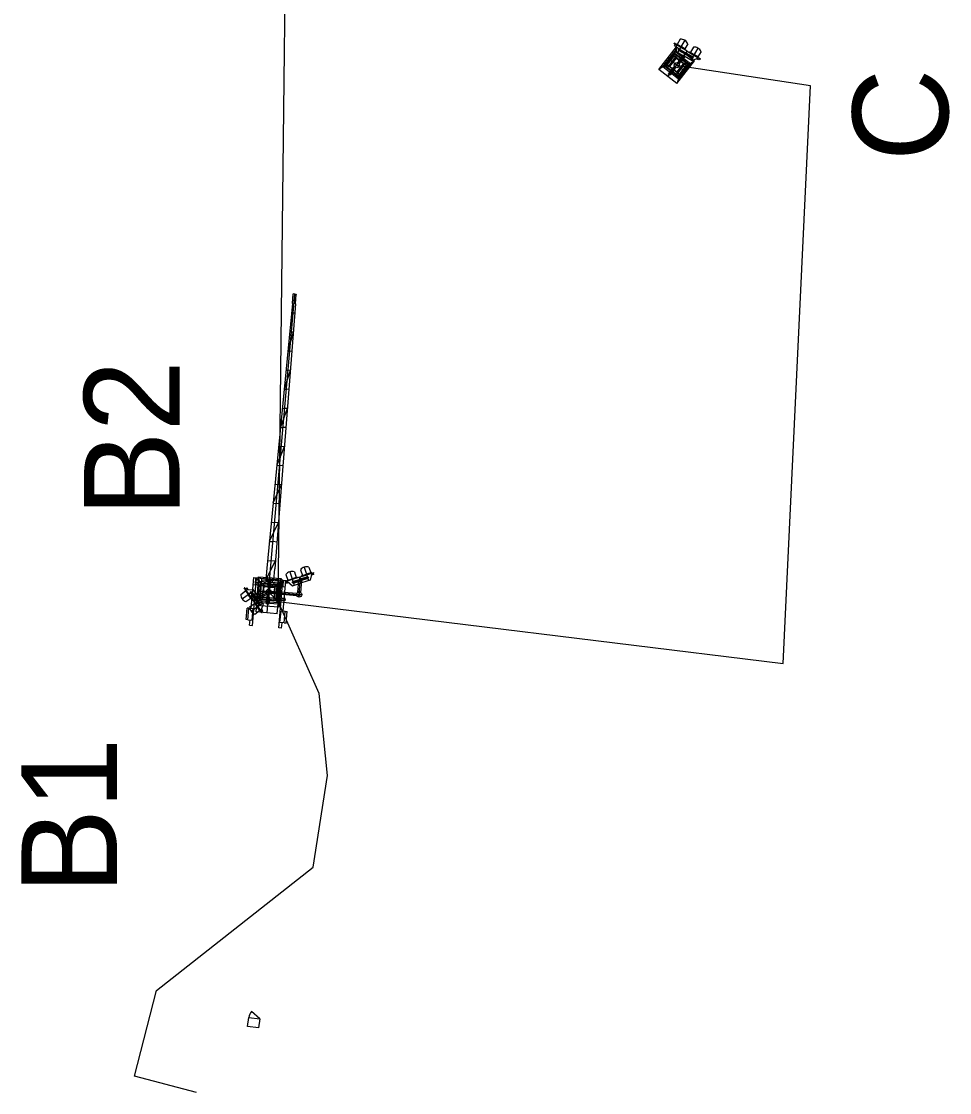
# Model space of a CAD drawing. Extents: x -717079 to -715675, y -957336 to -955099.
# Drawn here: x -716687.26 to -716663, y -956485.55 to -956457.54 of the extents above; entities that cross this region are included whole.
import ezdxf

# ---------------------------------------------------------------- set-up
doc = ezdxf.new("R2010")
doc.units = 0
doc.layers.add('TZ_PUPFL', color=7, linetype='Continuous')

msp = doc.modelspace()

# ---------------------------------------------------------------- linework, layer by layer
at = {"layer": 'TZ_PUPFL'}
for p, q in [((-716670.202, -956458.112), (-716670.2, -956458.108)), ((-716669.858, -956458.316), (-716670.202, -956458.112)), ((-716669.856, -956458.312), (-716670.2, -956458.108)), ((-716670.176, -956458.127), (-716670.199, -956458.166)), ((-716670.199, -956458.166), (-716670.149, -956458.196)), ((-716670.151, -956458.142), (-716670.144, -956458.327)), ((-716670.148, -956458.138), (-716670.141, -956458.126)), ((-716670.141, -956458.126), (-716670.02, -956458.197)), ((-716670.039, -956458.003), (-716670.119, -956458.138)), ((-716669.921, -956458.03), (-716670.11, -956458.348)), ((-716669.841, -956458.121), (-716669.922, -956458.256)), ((-716670.601, -956458.792), (-716670.138, -956458.202)), ((-716670.498, -956458.726), (-716670.177, -956458.317)), ((-716670.442, -956458.719), (-716670.17, -956458.373)), ((-716670.402, -956458.7), (-716670.179, -956458.417)), ((-716670.375, -956458.747), (-716670.128, -956458.432)), ((-716670.375, -956458.747), (-716670.128, -956458.432)), ((-716670.365, -956458.977), (-716669.902, -956458.387)), ((-716669.883, -956458.687), (-716670.198, -956458.44)), ((-716669.883, -956458.687), (-716670.198, -956458.44)), ((-716670.177, -956458.317), (-716670.138, -956458.202)), ((-716670.177, -956458.317), (-716670.004, -956458.453)), ((-716670.17, -956458.373), (-716670.177, -956458.317)), ((-716670.17, -956458.373), (-716670.025, -956458.487)), ((-716670.151, -956458.413), (-716670.018, -956458.518)), ((-716670.144, -956458.327), (-716669.938, -956458.45)), ((-716670.138, -956458.202), (-716669.666, -956458.572)), ((-716669.953, -956458.42), (-716670.103, -956458.611)), ((-716670.004, -956458.453), (-716670.103, -956458.611)), ((-716669.708, -956458.493), (-716670.086, -956458.269)), ((-716670.079, -956458.296), (-716669.907, -956458.398)), ((-716669.921, -956458.444), (-716670.071, -956458.635)), ((-716670.059, -956458.262), (-716669.887, -956458.364)), ((-716669.9, -956458.269), (-716670.02, -956458.197)), ((-716670.004, -956458.453), (-716669.953, -956458.42)), ((-716669.921, -956458.444), (-716669.953, -956458.42)), ((-716669.941, -956458.502), (-716669.921, -956458.444)), ((-716669.938, -956458.45), (-716669.856, -956458.312)), ((-716669.732, -956458.572), (-716669.938, -956458.45)), ((-716669.908, -956458.282), (-716669.9, -956458.269)), ((-716669.735, -956458.5), (-716669.907, -956458.398)), ((-716669.715, -956458.466), (-716669.887, -956458.364)), ((-716669.858, -956458.316), (-716669.515, -956458.521)), ((-716669.856, -956458.312), (-716669.512, -956458.517)), ((-716669.805, -956458.343), (-716669.797, -956458.33)), ((-716669.797, -956458.33), (-716669.677, -956458.402)), ((-716669.695, -956458.207), (-716669.775, -956458.343)), ((-716669.577, -956458.234), (-716669.766, -956458.552)), ((-716669.556, -956458.473), (-716669.677, -956458.402)), ((-716669.497, -956458.325), (-716669.578, -956458.46)), ((-716670.498, -956458.726), (-716670.601, -956458.792)), ((-716670.442, -956458.719), (-716670.498, -956458.726)), ((-716670.325, -956458.862), (-716670.498, -956458.726)), ((-716670.297, -956458.833), (-716670.442, -956458.719)), ((-716670.265, -956458.833), (-716670.398, -956458.728)), ((-716670.068, -956458.923), (-716670.383, -956458.676)), ((-716670.068, -956458.923), (-716670.383, -956458.676)), ((-716669.897, -956458.867), (-716670.369, -956458.497)), ((-716670.345, -956458.919), (-716670.195, -956458.729)), ((-716670.325, -956458.862), (-716670.195, -956458.729)), ((-716670.314, -956458.718), (-716670.141, -956458.498)), ((-716670.314, -956458.718), (-716670.22, -956458.792)), ((-716669.976, -956458.805), (-716670.291, -956458.558)), ((-716670.257, -956458.839), (-716670.01, -956458.525)), ((-716670.164, -956458.753), (-716670.195, -956458.729)), ((-716670.141, -956458.498), (-716670.047, -956458.572)), ((-716670.139, -956458.932), (-716669.892, -956458.617)), ((-716670.139, -956458.932), (-716669.892, -956458.617)), ((-716670.129, -956459.162), (-716669.666, -956458.572)), ((-716670.125, -956458.866), (-716669.952, -956458.646)), ((-716670.071, -956458.635), (-716670.103, -956458.611)), ((-716669.824, -956458.645), (-716670.096, -956458.991)), ((-716669.768, -956458.638), (-716670.089, -956459.047)), ((-716669.865, -956458.664), (-716670.087, -956458.947)), ((-716669.941, -956458.502), (-716670.071, -956458.635)), ((-716669.952, -956458.646), (-716670.047, -956458.572)), ((-716670.018, -956458.518), (-716669.868, -956458.636)), ((-716669.969, -956458.531), (-716669.824, -956458.645)), ((-716669.943, -956458.504), (-716669.768, -956458.638)), ((-716669.768, -956458.638), (-716669.824, -956458.645)), ((-716669.666, -956458.572), (-716669.768, -956458.638)), ((-716669.566, -956458.49), (-716669.732, -956458.572)), ((-716669.564, -956458.544), (-716669.614, -956458.514)), ((-716669.564, -956458.486), (-716669.556, -956458.473)), ((-716669.541, -956458.505), (-716669.564, -956458.544)), ((-716669.515, -956458.521), (-716669.512, -956458.517)), ((-716670.129, -956459.162), (-716670.601, -956458.792)), ((-716670.325, -956458.862), (-716670.345, -956458.919)), ((-716670.313, -956458.944), (-716670.345, -956458.919)), ((-716670.313, -956458.944), (-716670.164, -956458.753)), ((-716670.262, -956458.911), (-716670.313, -956458.944)), ((-716670.115, -956458.95), (-716670.265, -956458.833)), ((-716670.262, -956458.911), (-716670.164, -956458.753)), ((-716670.089, -956459.047), (-716670.262, -956458.911)), ((-716670.096, -956458.991), (-716670.241, -956458.877)), ((-716670.125, -956458.866), (-716670.22, -956458.792)), ((-716670.096, -956458.991), (-716670.089, -956459.047)), ((-716670.089, -956459.047), (-716670.129, -956459.162)), ((-716680.179, -956464.913), (-716680.85, -956471.831)), ((-716680.773, -956472.159), (-716680.118, -956464.667)), ((-716680.078, -956464.671), (-716680.203, -956465.162)), ((-716680.179, -956464.913), (-716680.157, -956464.664)), ((-716680.118, -956464.667), (-716680.157, -956464.664)), ((-716680.118, -956464.667), (-716680.078, -956464.671)), ((-716680.099, -956464.92), (-716680.078, -956464.671)), ((-716680.099, -956464.92), (-716680.64, -956471.849)), ((-716680.203, -956465.162), (-716680.161, -956465.165)), ((-716680.119, -956465.169), (-716680.161, -956465.165)), ((-716680.158, -956465.667), (-716680.3, -956466.157)), ((-716680.252, -956465.659), (-716680.205, -956465.663)), ((-716680.158, -956465.667), (-716680.205, -956465.663)), ((-716680.3, -956466.157), (-716680.248, -956466.161)), ((-716680.197, -956466.166), (-716680.248, -956466.161)), ((-716680.236, -956466.664), (-716680.396, -956467.152)), ((-716680.348, -956466.655), (-716680.292, -956466.66)), ((-716680.236, -956466.664), (-716680.292, -956466.66)), ((-716680.396, -956467.152), (-716680.335, -956467.158)), ((-716680.275, -956467.163), (-716680.335, -956467.158)), ((-716680.314, -956467.662), (-716680.493, -956468.148)), ((-716680.444, -956467.65), (-716680.379, -956467.656)), ((-716680.314, -956467.662), (-716680.379, -956467.656)), ((-716680.493, -956468.148), (-716680.423, -956468.154)), ((-716680.352, -956468.16), (-716680.423, -956468.154)), ((-716680.391, -956468.659), (-716680.589, -956469.143)), ((-716680.541, -956468.645), (-716680.466, -956468.652)), ((-716680.391, -956468.659), (-716680.466, -956468.652)), ((-716680.589, -956469.143), (-716680.51, -956469.15)), ((-716680.43, -956469.157), (-716680.51, -956469.15)), ((-716680.469, -956469.656), (-716680.686, -956470.138)), ((-716680.637, -956469.641), (-716680.553, -956469.648)), ((-716680.469, -956469.656), (-716680.553, -956469.648)), ((-716680.686, -956470.138), (-716680.597, -956470.146)), ((-716680.508, -956470.154), (-716680.597, -956470.146)), ((-716680.547, -956470.653), (-716680.782, -956471.134)), ((-716680.734, -956470.636), (-716680.64, -956470.644)), ((-716680.547, -956470.653), (-716680.64, -956470.644)), ((-716680.782, -956471.134), (-716680.684, -956471.142)), ((-716680.586, -956471.151), (-716680.684, -956471.142)), ((-716680.83, -956471.632), (-716680.728, -956471.641)), ((-716680.625, -956471.65), (-716680.876, -956472.129)), ((-716680.85, -956471.831), (-716680.876, -956472.129)), ((-716680.625, -956471.65), (-716680.728, -956471.641)), ((-716680.667, -956472.148), (-716680.64, -956471.849)), ((-716679.965, -956471.88), (-716679.917, -956472.03)), ((-716679.867, -956471.809), (-716679.754, -956472.161)), ((-716679.746, -956471.809), (-716679.698, -956471.959)), ((-716681.258, -956472.889), (-716681.188, -956472.082)), ((-716681.222, -956473.334), (-716681.113, -956472.089)), ((-716681.188, -956472.082), (-716680.351, -956472.155)), ((-716681.144, -956472.237), (-716681.133, -956472.107)), ((-716681.133, -956472.107), (-716681.111, -956472.089)), ((-716681.067, -956472.059), (-716681.129, -956472.807)), ((-716681.079, -956472.695), (-716681.037, -956472.177)), ((-716681.067, -956472.059), (-716680.469, -956472.108)), ((-716681.037, -956472.177), (-716681.067, -956472.059)), ((-716681.037, -956472.177), (-716680.818, -956472.195)), ((-716681, -956472.22), (-716681.037, -956472.177)), ((-716680.984, -956472.1), (-716680.998, -956472.269)), ((-716680.839, -956472.173), (-716680.979, -956472.271)), ((-716680.876, -956472.129), (-716680.667, -956472.148)), ((-716680.838, -956472.153), (-716680.839, -956472.173)), ((-716680.768, -956472.084), (-716680.83, -956472.831)), ((-716680.769, -956472.119), (-716680.828, -956472.79)), ((-716680.818, -956472.195), (-716680.793, -956472.139)), ((-716680.818, -956472.195), (-716680.813, -956472.381)), ((-716680.793, -956472.139), (-716680.813, -956472.381)), ((-716680.793, -956472.139), (-716680.753, -956472.143)), ((-716680.753, -956472.143), (-716680.773, -956472.384)), ((-716680.738, -956472.202), (-716680.753, -956472.143)), ((-716680.708, -956472.164), (-716680.71, -956472.184)), ((-716680.71, -956472.184), (-716680.59, -956472.305)), ((-716680.555, -956472.137), (-716680.57, -956472.307)), ((-716680.535, -956473.394), (-716680.426, -956472.149)), ((-716680.469, -956472.108), (-716680.531, -956472.856)), ((-716680.519, -956472.219), (-716680.469, -956472.108)), ((-716680.41, -956472.17), (-716680.428, -956472.149)), ((-716680.422, -956472.962), (-716680.351, -956472.155)), ((-716680.421, -956472.3), (-716680.41, -956472.17)), ((-716679.993, -956472.07), (-716680.374, -956472.192)), ((-716680.373, -956472.196), (-716680.374, -956472.192)), ((-716679.992, -956472.074), (-716680.373, -956472.196)), ((-716680.346, -956472.002), (-716680.298, -956472.152)), ((-716680.343, -956472.187), (-716680.33, -956472.23)), ((-716680.321, -956472.159), (-716680.188, -956472.117)), ((-716680.317, -956472.174), (-716680.321, -956472.159)), ((-716680.315, -956472.178), (-716680.173, -956472.296)), ((-716680.248, -956471.931), (-716680.135, -956472.283)), ((-716680.055, -956472.074), (-716680.188, -956472.117)), ((-716679.759, -956472.079), (-716680.178, -956472.213)), ((-716680.165, -956472.188), (-716679.975, -956472.127)), ((-716680.153, -956472.226), (-716679.963, -956472.165)), ((-716680.127, -956471.932), (-716680.079, -956472.082)), ((-716680.05, -956472.088), (-716680.055, -956472.074)), ((-716680.037, -956472.471), (-716680.009, -956472.143)), ((-716679.929, -956472.15), (-716680.009, -956472.143)), ((-716680.008, -956472.593), (-716679.965, -956472.106)), ((-716679.993, -956472.07), (-716679.612, -956471.948)), ((-716679.944, -956472.222), (-716679.993, -956472.07)), ((-716679.992, -956472.074), (-716679.611, -956471.952)), ((-716679.784, -956472.066), (-716679.975, -956472.127)), ((-716679.772, -956472.104), (-716679.963, -956472.165)), ((-716679.958, -956472.478), (-716679.929, -956472.15)), ((-716679.716, -956472.149), (-716679.944, -956472.222)), ((-716679.941, -956472.037), (-716679.807, -956471.995)), ((-716679.936, -956472.052), (-716679.941, -956472.037)), ((-716679.674, -956471.952), (-716679.807, -956471.995)), ((-716679.668, -956471.97), (-716679.716, -956472.149)), ((-716679.626, -956472.004), (-716679.682, -956472.022)), ((-716679.669, -956471.966), (-716679.674, -956471.952)), ((-716679.64, -956471.961), (-716679.626, -956472.004)), ((-716679.611, -956471.952), (-716679.612, -956471.948)), ((-716681.528, -956472.521), (-716681.4, -956472.43)), ((-716681.492, -956472.636), (-716681.191, -956472.422)), ((-716681.433, -956472.349), (-716681.437, -956472.352)), ((-716681.205, -956472.678), (-716681.437, -956472.352)), ((-716681.201, -956472.675), (-716681.433, -956472.349)), ((-716681.415, -956472.374), (-716681.379, -956472.348)), ((-716681.402, -956472.401), (-716681.414, -956472.409)), ((-716681.414, -956472.409), (-716681.333, -956472.523)), ((-716681.398, -956472.398), (-716681.214, -956472.389)), ((-716681.379, -956472.348), (-716681.345, -956472.395)), ((-716681.267, -956472.452), (-716681.012, -956472.81)), ((-716681.239, -956472.457), (-716681.124, -956472.62)), ((-716681.214, -956472.389), (-716681.075, -956472.585)), ((-716681.204, -956472.261), (-716680.785, -956472.298)), ((-716680.865, -956472.446), (-716681.158, -956472.596)), ((-716681.144, -956472.237), (-716681.126, -956472.258)), ((-716681.121, -956472.981), (-716681.074, -956472.443)), ((-716681.098, -956472.433), (-716680.5, -956472.482)), ((-716681.074, -956472.443), (-716680.865, -956472.462)), ((-716681.036, -956472.659), (-716681, -956472.22)), ((-716681.014, -956472.619), (-716680.999, -956472.45)), ((-716681, -956472.22), (-716680.817, -956472.235)), ((-716680.999, -956472.45), (-716680.983, -956472.261)), ((-716680.998, -956472.269), (-716680.979, -956472.271)), ((-716680.6, -956472.475), (-716680.998, -956472.44)), ((-716680.6, -956472.475), (-716680.998, -956472.44)), ((-716680.986, -956472.292), (-716680.587, -956472.324)), ((-716680.587, -956472.325), (-716680.985, -956472.291)), ((-716680.931, -956472.245), (-716680.966, -956472.644)), ((-716680.932, -956472.246), (-716680.965, -956472.644)), ((-716680.961, -956472.242), (-716680.602, -956472.274)), ((-716680.928, -956472.326), (-716680.939, -956472.455)), ((-716680.649, -956472.35), (-716680.928, -956472.326)), ((-716680.865, -956472.452), (-716679.936, -956472.533)), ((-716680.858, -956472.488), (-716680.74, -956472.427)), ((-716680.782, -956472.258), (-716680.847, -956473.005)), ((-716680.829, -956472.398), (-716680.769, -956472.517)), ((-716680.813, -956472.381), (-716680.773, -956472.384)), ((-716680.793, -956472.391), (-716680.805, -956472.524)), ((-716680.367, -956472.335), (-716680.785, -956472.298)), ((-716680.738, -956472.202), (-716680.773, -956472.384)), ((-716680.748, -956472.415), (-716680.744, -956472.411)), ((-716680.746, -956472.241), (-716680.562, -956472.256)), ((-716680.738, -956472.202), (-716680.519, -956472.219)), ((-716680.734, -956472.473), (-716680.526, -956472.491)), ((-716680.732, -956472.433), (-716680.059, -956472.492)), ((-716680.632, -956472.271), (-716680.667, -956472.67)), ((-716680.633, -956472.27), (-716680.666, -956472.669)), ((-716680.649, -956472.35), (-716680.66, -956472.48)), ((-716680.584, -956472.296), (-716680.601, -956472.485)), ((-716680.562, -956472.256), (-716680.598, -956472.695)), ((-716680.57, -956472.307), (-716680.59, -956472.305)), ((-716680.562, -956472.256), (-716680.519, -956472.219)), ((-716680.519, -956472.219), (-716680.561, -956472.738)), ((-716680.421, -956472.3), (-716680.443, -956472.318)), ((-716680.33, -956472.23), (-716680.274, -956472.212)), ((-716680.173, -956472.296), (-716679.944, -956472.222)), ((-716679.996, -956472.461), (-716680.008, -956472.593)), ((-716680.002, -956472.452), (-716680.003, -956472.461)), ((-716679.989, -956472.454), (-716679.99, -956472.462)), ((-716681.395, -956472.708), (-716681.267, -956472.617)), ((-716681.252, -956472.637), (-716681.333, -956472.523)), ((-716681.296, -956472.847), (-716681.168, -956472.755)), ((-716681.272, -956472.48), (-716681.156, -956472.643)), ((-716681.26, -956472.962), (-716680.959, -956472.748)), ((-716681.256, -956472.578), (-716681.259, -956472.608)), ((-716681.259, -956472.608), (-716681.09, -956472.623)), ((-716681.256, -956472.578), (-716681.254, -956472.548)), ((-716680.37, -956472.656), (-716681.256, -956472.578)), ((-716681.254, -956472.548), (-716681.084, -956472.563)), ((-716681.24, -956472.629), (-716681.252, -956472.637)), ((-716680.393, -956472.653), (-716681.23, -956472.58)), ((-716681.075, -956472.585), (-716681.205, -956472.678)), ((-716681.205, -956472.678), (-716680.973, -956473.003)), ((-716681.201, -956472.675), (-716680.969, -956473.001)), ((-716681.17, -956472.726), (-716681.182, -956472.735)), ((-716681.182, -956472.735), (-716681.101, -956472.849)), ((-716680.858, -956472.488), (-716681.175, -956472.649)), ((-716681.158, -956472.596), (-716681.122, -956472.667)), ((-716681.04, -956472.806), (-716681.156, -956472.643)), ((-716681.129, -956472.807), (-716681.079, -956472.695)), ((-716681.008, -956472.783), (-716681.124, -956472.62)), ((-716680.828, -956472.517), (-716681.122, -956472.667)), ((-716680.551, -956472.78), (-716681.099, -956472.732)), ((-716681.079, -956472.695), (-716681.036, -956472.659)), ((-716680.86, -956472.71), (-716681.079, -956472.695)), ((-716680.936, -956472.78), (-716681.075, -956472.585)), ((-716680.853, -956472.674), (-716681.036, -956472.659)), ((-716680.613, -956472.624), (-716681.011, -956472.589)), ((-716681.011, -956472.591), (-716680.612, -956472.623)), ((-716680.637, -956472.672), (-716680.996, -956472.641)), ((-716680.869, -956472.486), (-716680.861, -956472.482)), ((-716680.863, -956472.497), (-716680.855, -956472.493)), ((-716680.86, -956472.713), (-716680.825, -956472.53)), ((-716680.86, -956472.713), (-716680.845, -956472.772)), ((-716680.845, -956472.772), (-716680.825, -956472.53)), ((-716680.825, -956472.53), (-716680.785, -956472.534)), ((-716680.805, -956472.775), (-716680.785, -956472.534)), ((-716680.78, -956472.72), (-716680.805, -956472.775)), ((-716680.78, -956472.72), (-716680.785, -956472.534)), ((-716680.598, -956472.695), (-716680.781, -956472.68)), ((-716680.561, -956472.738), (-716680.78, -956472.72)), ((-716680.756, -956472.508), (-716680.753, -956472.512)), ((-716680.737, -956472.493), (-716680.064, -956472.552)), ((-716680.601, -956472.485), (-716680.616, -956472.654)), ((-716680.598, -956472.695), (-716680.561, -956472.738)), ((-716680.573, -956473.029), (-716680.526, -956472.491)), ((-716680.561, -956472.738), (-716680.531, -956472.856)), ((-716680.372, -956472.685), (-716680.542, -956472.671)), ((-716680.367, -956472.626), (-716680.536, -956472.611)), ((-716680.37, -956472.656), (-716680.372, -956472.685)), ((-716680.37, -956472.656), (-716680.367, -956472.626)), ((-716679.936, -956472.533), (-716680.068, -956472.521)), ((-716681.389, -956473.179), (-716681.363, -956472.88)), ((-716681.313, -956472.884), (-716681.363, -956472.88)), ((-716681.339, -956473.183), (-716681.313, -956472.884)), ((-716681.313, -956472.884), (-716681.204, -956472.894)), ((-716681.23, -956473.193), (-716681.204, -956472.894)), ((-716681.163, -956473.034), (-716681.035, -956472.943)), ((-716680.531, -956472.856), (-716681.129, -956472.807)), ((-716680.573, -956473.029), (-716681.121, -956472.981)), ((-716681.02, -956472.963), (-716681.101, -956472.849)), ((-716681.008, -956472.955), (-716681.02, -956472.963)), ((-716681.004, -956472.952), (-716680.936, -956472.78)), ((-716680.987, -956472.976), (-716680.951, -956472.95)), ((-716680.951, -956472.95), (-716680.984, -956472.902)), ((-716680.969, -956473.001), (-716680.973, -956473.003)), ((-716680.845, -956472.772), (-716680.805, -956472.775)), ((-716680.503, -956473.256), (-716680.476, -956472.957)), ((-716680.367, -956472.967), (-716680.476, -956472.957)), ((-716680.393, -956473.266), (-716680.367, -956472.967)), ((-716680.367, -956472.967), (-716680.317, -956472.971)), ((-716680.343, -956473.27), (-716680.317, -956472.971)), ((-716681.339, -956473.183), (-716681.389, -956473.179)), ((-716681.339, -956473.183), (-716681.23, -956473.193)), ((-716681.297, -956473.327), (-716681.285, -956473.188)), ((-716680.393, -956473.266), (-716680.503, -956473.256)), ((-716680.46, -956473.401), (-716680.448, -956473.261)), ((-716680.393, -956473.266), (-716680.343, -956473.27)), ((-716681.297, -956473.327), (-716681.222, -956473.334)), ((-716680.46, -956473.401), (-716680.535, -956473.394))]:
    msp.add_line(p, q, dxfattribs=at)
for points in [[(-716682.682, -956485.549), (-716684.309, -956485.117), (-716683.726, -956482.879), (-716679.632, -956479.652), (-716679.258, -956477.256), (-716679.479, -956475.115), (-716680.551, -956472.706), (-716680.325, -956453.033), (-716678.96, -956448.869), (-716678.546, -956442.387), (-716678.608, -956440.175), (-716669.501, -956440.378), (-716668.747, -956441.71)], [(-716682.682, -956485.549), (-716684.309, -956485.117), (-716683.726, -956482.879), (-716679.632, -956479.652), (-716679.258, -956477.256), (-716679.479, -956475.115), (-716680.551, -956472.706), (-716680.325, -956453.033), (-716678.816, -956452.936), (-716678.701, -956454.708)], [(-716682.682, -956485.549), (-716684.309, -956485.117), (-716683.726, -956482.879), (-716679.632, -956479.652), (-716679.258, -956477.256), (-716679.479, -956475.115), (-716680.551, -956472.706), (-716667.354, -956474.331), (-716666.634, -956459.221), (-716670.148, -956458.687)], [(-716681.111, -956472.089), (-716680.769, -956472.119)], [(-716680.987, -956472.14), (-716680.773, -956472.159)], [(-716680.559, -956472.177), (-716680.773, -956472.159)], [(-716680.428, -956472.149), (-716680.769, -956472.119)], [(-716682.682, -956485.549), (-716684.309, -956485.117), (-716683.726, -956482.879), (-716679.632, -956479.652), (-716679.258, -956477.256), (-716679.479, -956475.115), (-716680.551, -956472.706), (-716680.799, -956472.454)], [(-716681.126, -956472.258), (-716680.998, -956472.269)], [(-716680.443, -956472.318), (-716680.57, -956472.307)], [(-716681.03, -956483.621), (-716681.061, -956483.859), (-716681.349, -956483.821), (-716681.318, -956483.583), (-716681.03, -956483.621)], [(-716681.03, -956483.621), (-716681.244, -956483.425)]]:
    msp.add_lwpolyline(points, dxfattribs=at)
for centre, radius in [((-716670.159, -956458.471), 0.0135), ((-716670.069, -956458.279), 0.02), ((-716669.725, -956458.483), 0.02), ((-716670.344, -956458.707), 0.0135), ((-716670.133, -956458.682), 0.0665), ((-716669.923, -956458.656), 0.0135), ((-716670.108, -956458.893), 0.0135), ((-716681.102, -956472.135), 0.012), ((-716680.445, -956472.192), 0.012), ((-716680.159, -956472.207), 0.02), ((-716679.778, -956472.085), 0.02), ((-716681.256, -956472.468), 0.02), ((-716681.109, -956472.214), 0.012), ((-716680.936, -956472.296), 0.0135), ((-716680.799, -956472.457), 0.0665), ((-716680.637, -956472.32), 0.0135), ((-716680.452, -956472.272), 0.012), ((-716680.002, -956472.527), 0.0665), ((-716680.961, -956472.595), 0.0135), ((-716680.662, -956472.619), 0.0135), ((-716681.024, -956472.794), 0.02)]:
    msp.add_circle(centre, radius, dxfattribs=at)
for centre, radius, start, end in [((-716670.02, -956458.197), 0.195, 59.2583, 95.3972), ((-716670.02, -956458.197), 0.195, 23.1195, 59.2583), ((-716670.164, -956458.429), 0.02, 51.8781, 141.8781), ((-716669.677, -956458.402), 0.195, 59.2583, 95.3972), ((-716669.677, -956458.402), 0.195, 23.1195, 59.2583), ((-716670.386, -956458.712), 0.02, 141.8781, 231.8781), ((-716669.88, -956458.651), 0.02, 321.8781, 51.8781), ((-716670.103, -956458.935), 0.02, 231.8781, 321.8781), ((-716679.807, -956471.995), 0.195, 107.7815, 143.9203), ((-716679.807, -956471.995), 0.195, 71.6427, 107.7815), ((-716680.188, -956472.117), 0.195, 107.7815, 143.9203), ((-716680.188, -956472.117), 0.195, 71.6427, 107.7815), ((-716679.969, -956472.146), 0.04, 355, 175), ((-716680.963, -956472.262), 0.02, 85.0025, 175.0025), ((-716680.799, -956472.457), 0.075, 174.7886, 207.0195), ((-716680.799, -956472.457), 0.0665, 170.0418, 243.9972), ((-716680.799, -956472.457), 0.0665, 309.9997, 39.9999), ((-716680.799, -956472.457), 0.0715, 309.9997, 39.9999), ((-716680.604, -956472.294), 0.02, 355.0025, 85.0025), ((-716680.002, -956472.527), 0.0665, 48.0223, 121.9777), ((-716680.002, -956472.527), 0.075, 85, 117.231), ((-716680.002, -956472.527), 0.075, 52.769, 85), ((-716681.333, -956472.523), 0.195, 179.2909, 215.4298), ((-716681.333, -956472.523), 0.195, 215.4298, 251.5686), ((-716681.14, -956472.631), 0.04, 117.0195, 297.0195), ((-716680.994, -956472.621), 0.02, 175.0025, 265.0025), ((-716680.799, -956472.457), 0.075, 207.0195, 239.2505), ((-716680.635, -956472.652), 0.02, 265.0025, 355.0025), ((-716681.101, -956472.849), 0.195, 179.2909, 215.4298), ((-716681.101, -956472.849), 0.195, 215.4298, 251.5686), ((-716681.03, -956483.621), 0.29, 137.5628, 172.5656)]:
    msp.add_arc(centre, radius, start, end, dxfattribs=at)

# ---------------------------------------------------------------- texts
for s, height, rotation, p in [('TIZ', 0.02, 141.8781, (-716670.354, -956458.947)), ('C', 2.5, 90, (-716663.036, -956461.191)), ('B2', 2.5, 90, (-716683.127, -956470.49)), ('TIZ', 0.02, 355.3191, (-716680.761, -956472.114)), ('B1', 2.5, 90, (-716684.761, -956480.361))]:
    msp.add_text(s, height=height, rotation=rotation, dxfattribs=at).set_placement(p)

doc.saveas('drawing.dxf')
